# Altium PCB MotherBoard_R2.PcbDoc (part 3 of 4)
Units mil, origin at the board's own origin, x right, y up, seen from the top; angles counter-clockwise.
Board outline 9500 x 4600 mil, 4 copper layers (Top Layer, Power Layer, GND Layer, Bottom Layer), stack 61.6 mil thick; 206 components, 289 nets, 935 pads, 328 vias.
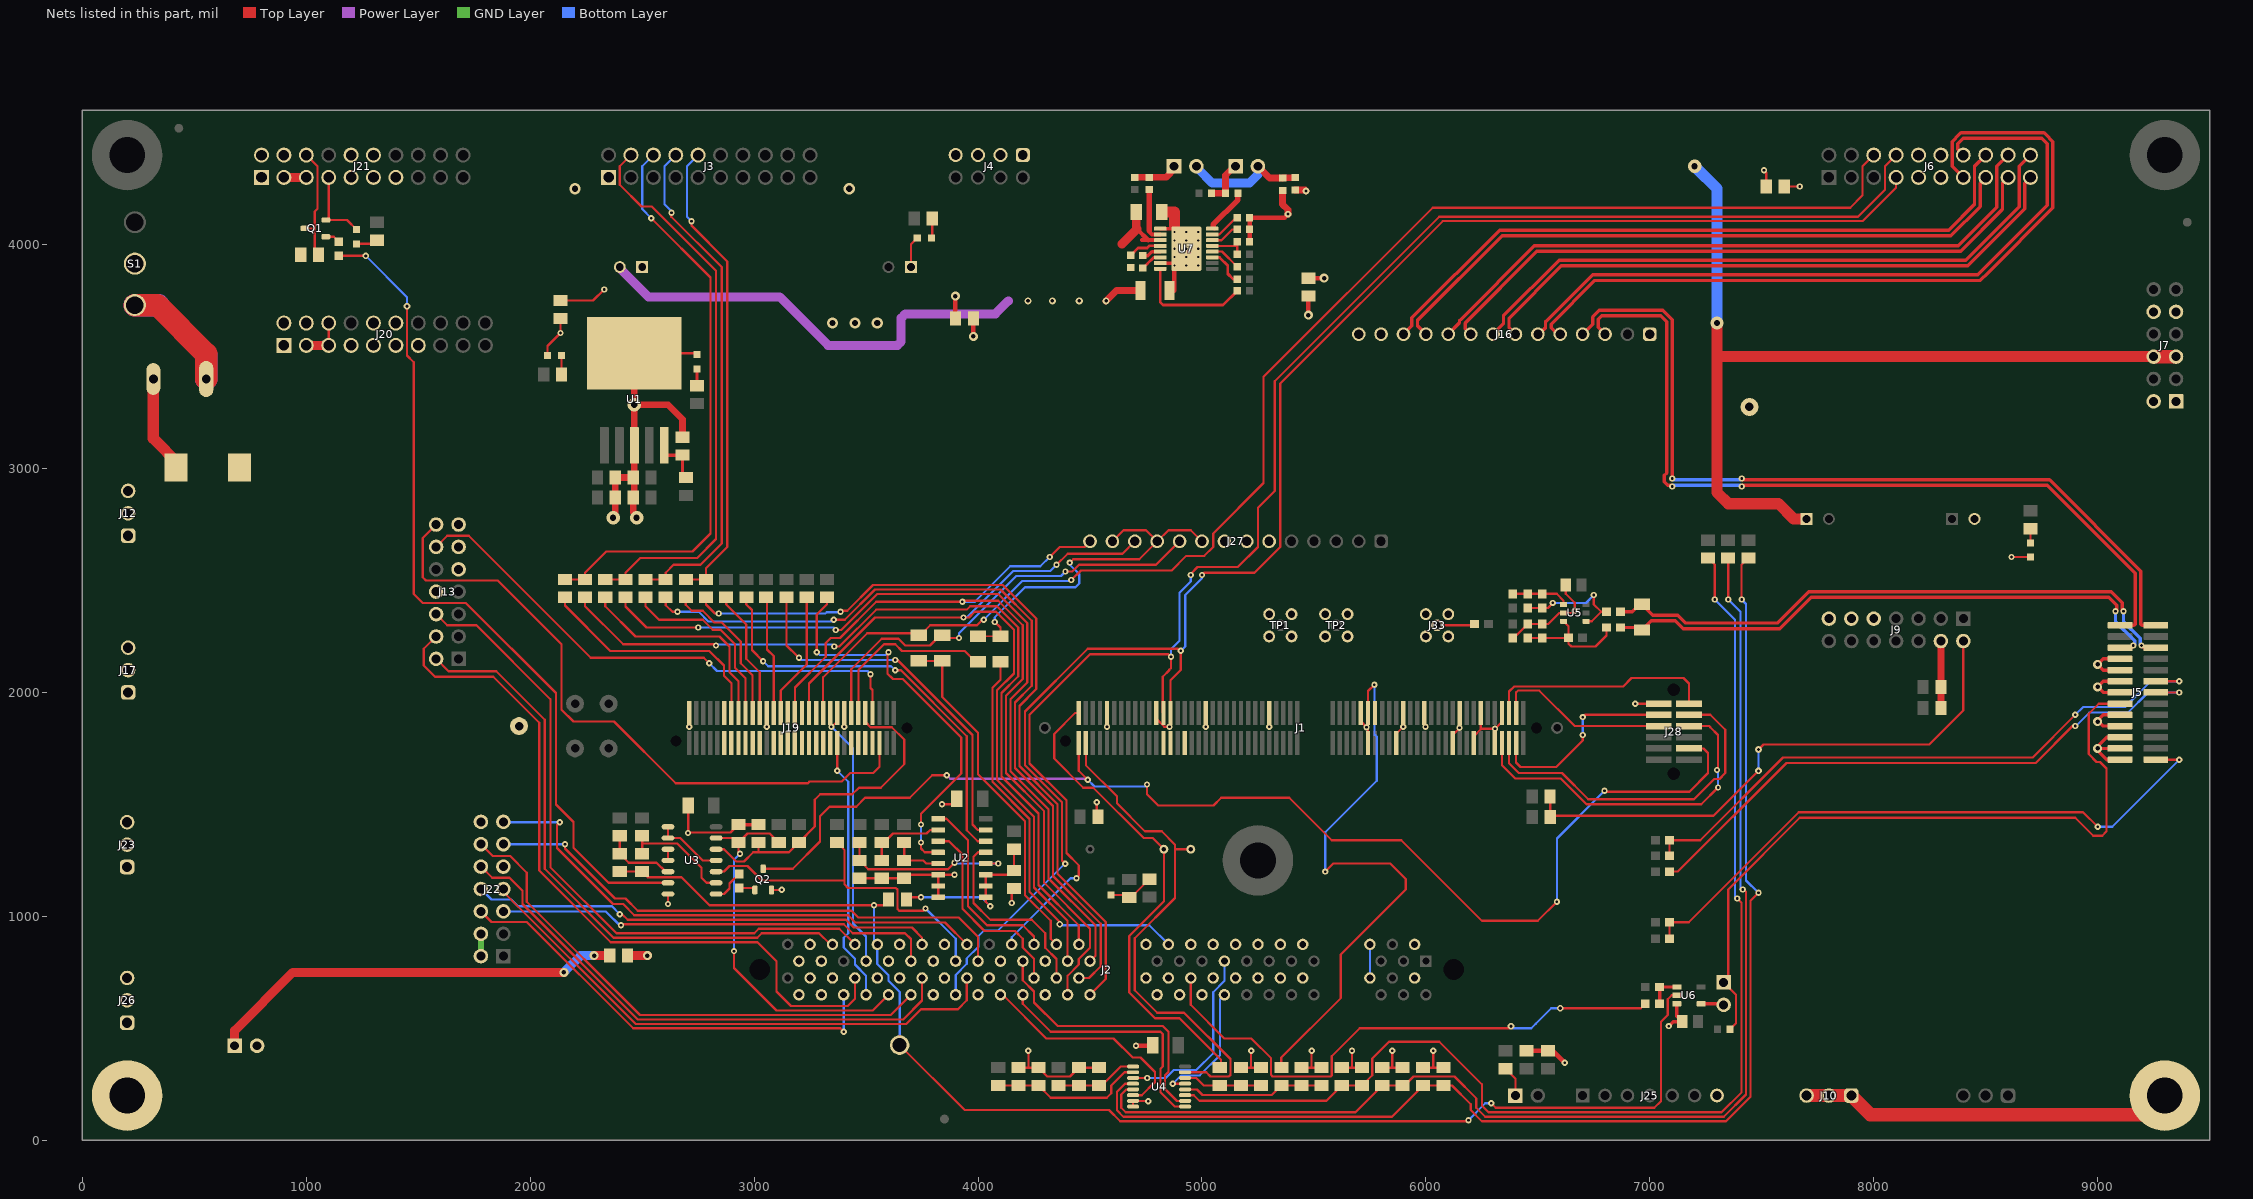
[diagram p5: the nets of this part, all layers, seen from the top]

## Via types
v1: diameter 28, hole 12, Top Layer to Bottom Layer, 238 vias
v2: diameter 40, hole 20, Top Layer to Bottom Layer, 21 vias
v3: diameter 30, hole 14, Top Layer to Bottom Layer, 19 vias
v4: diameter 28, hole 12, Top Layer to Bottom Layer, tented top, 16 vias
v5: diameter 22, hole 10, Top Layer to Bottom Layer, tented both sides, 12 vias
v6: diameter 60, hole 28, Top Layer to Bottom Layer, 9 vias
v7: diameter 50, hole 28, Top Layer to Bottom Layer, 5 vias
v8: diameter 32, hole 16, Top Layer to Bottom Layer, tented top, 4 vias
v9: diameter 22, hole 10, Top Layer to Bottom Layer, 3 vias
v10: diameter 30, hole 14, Top Layer to Bottom Layer, tented top, 1 vias

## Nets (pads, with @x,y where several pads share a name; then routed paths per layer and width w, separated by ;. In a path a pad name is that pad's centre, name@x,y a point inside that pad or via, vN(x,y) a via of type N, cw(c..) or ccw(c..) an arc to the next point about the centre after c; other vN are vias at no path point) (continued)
C2K_GPIO61: J13.14 J19.126 | length 2989.1
  Top Layer w10: J13.14@1579.98,2750 1520,2690.02 1520,2515 1535,2500 1855,2500 2139.92,2215.08 2139.92,1923.33 2193.25,1870 2374.61,1870 2649.61,1595 3240.05,1595 3247.17,1602.13 3391.55,1602.13 3429.42,1640 3532.01,1640 3560.01,1668 J19.126@3560.01,1775
C2K_GPIO62: J13.12 J19.127 | length 2393.2
  Top Layer w10: J13.12@1579.98,2650 1629.98,2700 1725,2700 2270,2155 2775,2155 v1(2800,2130) ; v1(3520,2081.76) 3520,2020 3528.51,2011.49 J19.127@3528.51,1908.86
  Bottom Layer w10: v1(2800,2130) 2834.25,2095.75 3506.01,2095.75 v1(3520,2081.76)
C2K_GPIO63: J19.128
C2K_GPIO64: J19.129 R30.1 R82.2 U3.12 | length 1513.4
  Top Layer w10: U3.12@2830,1300 2865,1300 2920,1245 2955,1245 2996,1286 3020,1286 ; R82.2@3020,1330 3020,1286 ; J19.129@3497.02,1908.86 3497.02,1867.98 3520,1845 3615,1845 3670,1790 3670,1680 3565,1575 3467.79,1575 3437.79,1545 3295,1545 3271,1521 3271,1401 R30.1@3200,1330 3156,1286 3020,1286
C2K_GPIO65: J19.130
C2K_GPIO66: J19.131 R85.1 | length 805.6
  Top Layer w10: J19.131@3465.52,1908.86 3465.52,2100.52 3580,2215 3630,2215 3660,2185 3940,2185 3987.23,2137.77 R85.1@4000,2137.77
C2K_GPIO67: J19.132
C2K_GPIO68: J19.133 J27.10 R21.2 | length 1945.3
  Top Layer w10: J19.133@3434.02,1908.86 3434.02,2104.02 3570,2240 3645,2240 3675,2210 3785,2210 3830,2255 R21.2@3840,2255 3851.99,2243.01 v1(3915,2243.01) ; v4(4390,2540) 4420.83,2540 4450.83,2570 4795,2570 J27.10@4900,2675
  Bottom Layer w10: v1(3915,2243.01) 3915,2265 4170,2520 4370,2520 v4(4390,2540)
C2K_GPIO69: J19.134
C2K_GPIO70: J2.43 J19.137 | length 1185.1
  Top Layer w10: v1(3345,1847.09) 3347.09,1847.09 3371.03,1871.03 J19.137@3371.03,1908.86
  Bottom Layer w10: v1(3345,1847.09) 3441.7,1750.39 3441.7,968.3 3500,910 J2.43@3500,800
C2K_GPIO71: J2.93 J19.138 | length 1195
  Top Layer w10: v1(3371.03,1650) J19.138@3371.03,1775
  Bottom Layer w10: v1(3371.03,1650) 3420,1601.03 3420,924.47 3400,904.47 3400,861.31 3450,811.31 3450,785.46 3500,735.46 J2.93@3500,650
C2K_GPIO72: J19.139
C2K_GPIO73: J19.140
C2K_GPIO74: J6.6 J19.141 R20.2 | length 6218.5
  Top Layer w10: J19.141@3308.04,1908.86 3308.04,2067.62 3505.42,2265 3725,2265 R20.2@3735,2255 3741.54,2255 3786.54,2300 3995,2300 4022.43,2327.43 4024.86,2325 v1(4025,2325) ; v4@4414.96,2502.47 v4(4416.75,2502.47) 4459.28,2545 4865.25,2545 4930.25,2610 5010,2610 5050,2650 5050,2710 5275,2935 5275,3410 6030,4165 7895,4165 7950,4220 7950,4350 J6.6@8000,4400
  Bottom Layer w10: v1(4025,2325) 4197.47,2497.47 4411.75,2497.47 v4(4416.75,2502.47)
C2K_GPIO76: J19.143
C2K_GPIO77: J19.144
C2K_GPIO78: J2.25 J19.145 J27.12 | length 3758.8
  Top Layer w10: J19.145@3245.05,1908.86 3245.05,2040.05 3540,2335 v1(3935.37,2335) 3960,2335 3985,2360 4080,2360 4160,2280 4160,2085 4085,2010 4085,1610.28 4250,1445.28 4250,1128.92 4400,978.92 J2.25@4400,800 ; v1(4350,2570) 4400,2620 4645,2620 J27.12@4700,2675
  Bottom Layer w10: v1(3935.37,2335) 3950,2335 4157.57,2542.57 4322.57,2542.57 v1(4350,2570)
C2K_GPIO79: J19.146
C2K_GPIO80: J19.147
C2K_GPIO81: J19.148
C2K_GPIO82: J2.75 J19.149 J27.14 | length 3938.7
  Top Layer w10: J19.149@3182.05,1908.86 3182.05,2022.05 3320,2160 3320,2221.24 3341.77,2243.01 3383.01,2243.01 3545,2405 v1@3925,2405 ; v1(3930,2405) 3925,2410 4090,2410 4200,2300 4200,2059.99 4125,1984.99 4125,1640 4295,1470 4295,1150 4500,945 4500,860 4450,810 4450,785 4400,735 J2.75@4400,650 ; v1(4320,2605) 4365,2650 4475,2650 J27.14@4500,2675
  Bottom Layer w10: v1(3930,2405) 3929.63,2405.37 3985.37,2405.37 4143.25,2563.25 4278.25,2563.25 v1(4320,2605)
C2K_GPIO83: J19.150
C2K_GPIO84: J19.151
C2K_GPIO85: J19.152
C2K_GPIO86: J19.153 R14.1 | length 564.2
  Top Layer w10: J19.153@3119.06,1908.86 3119.06,2009.06 3235,2125 R14.1@3235,2425
C2K_GPIO87: J19.154
C2K_GPIO88: J19.155 R18.1 | length 528.6
  Top Layer w10: R18.1@3057.6,2425 3057.6,2192.4 3087.57,2162.43 J19.155@3087.57,1908.86
C2K_GPIO89: J19.156
C2K_GPIO90: J19.159 R16.1 | length 578.1
  Top Layer w10: R16.1@2875,2425 2875,2393.09 2965,2303.09 2965,2150 3024.57,2090.43 J19.159@3024.57,1908.86
C2K_GPIO91: J19.160
C2K_GPIO92: J19.161 R12.1 | length 686.9
  Top Layer w10: R12.1@2695,2425 2695,2391.87 2721.87,2365 2770,2365 2822.4,2312.6 2855,2312.6 2940,2227.6 2940,2130 2993.08,2076.92 J19.161@2993.08,1908.86
C2K_GPIO93: J19.162
C2K_GPIO94: J19.163 R10.1 | length 835.9
  Top Layer w10: R10.1@2515,2425 2515,2385 2575,2325 2770,2325 2815,2280 2850,2280 2915,2215 2915,2110 2961.58,2063.42 J19.163@2961.58,1908.86
C2K_GPIO95: J19.168
C2K_GPIO96: J1.93 J2.85 J6.7 | length 7357.5
  Top Layer w10: v1(4389.32,1235.68) 4375,1250 4375,1510 4210,1675 4210,1915 4490,2195 4891.51,2195 4900.75,2185.75 v1(4905,2185.75) 4905,2100 4859.45,2054.45 J1.93@4859.45,1908.86 ; v4(5000,2525) 5010,2535 5235,2535 5350,2650 5350,3380 6075,4105 7949.79,4105 8100,4255.21 J6.7@8100,4300
  Bottom Layer w10: J2.85@3900,650 3900,738.54 3950,788.54 3950,812.46 4001,863.46 4001,911 4026,936 4088,936 4387.68,1235.68 v1(4389.32,1235.68) ; v1(4905,2185.75) 4925,2205.75 4925,2435 5000,2510 v4(5000,2525)
C2K_GPIO97: J1.94
C2K_GPIO98: J1.95 J2.30 J6.8 | length 7054.7
  Top Layer w10: v1(4440,1170) 4450,1180 4450,1227.85 4395,1282.85 4395,1518.28 4230,1683.28 4230,1900 4500.23,2170.23 4850.23,2170.23 v1(4861.45,2159.02) 4861.45,2108.69 4853.88,2101.12 4855,2100 4825,2070 4825,1911.81 J1.95@4827.95,1908.86 ; v4(4950,2525) 4950,2529.57 4980.43,2560 5160,2560 5250,2650 5250,2825 5325,2900 5325,3390 6060,4125 7930,4125 8050,4245 8050,4350 J6.8@8100,4400
  Bottom Layer w10: J2.30@4150,875 4150,907 4413,1170 v1(4440,1170) ; v1(4861.45,2159.02) 4861.45,2192.78 4900,2231.33 4900,2445.39 4950,2495.39 v4(4950,2525)
C2K_GPIO99: J1.96
C2K_GPIO104: J19.169
C2K_GPIO107: J19.170
C2K_GPIO125: J1.90
C2K_GPIO126: J19.142
C2K_GPIO127: J19.165 R6.1 | length 982.3
  Top Layer w10: R6.1@2335,2425 2335,2385 2470,2250 2845,2250 2890,2205 2890,2090 2930.09,2049.91 J19.165@2930.09,1908.86
C2K_GPIO128: J19.166
C2K_GPIO133: J19.164
C2K_GPIO147: J19.167 R8.1 | length 1082.7
  Top Layer w10: R8.1@2155,2425 2155,2388.6 2358.94,2184.66 2800.34,2184.66 2865,2120 2865,2074.44 2898.59,2040.85 J19.167@2898.59,1908.86
C2K_TCK: J1.5 J28.2 | length 1024.4
  Top Layer w10: J1.5@6371.26,1908.86 6371.26,2003.86 6393.55,2026.15 6879.86,2026.15 6918.71,2065 7150,2065 7175,2040 J28.2@7175,1950
C2K_TDI: J1.8 J28.6 | length 1552.9
  Top Layer w10: J1.8@6339.76,1775 6339.76,1675.24 6399,1616 6602,1616 6717,1501 7230,1501 v1(7305,1576) ; J28.6@7175,1850 7265,1850 7270,1845 7305,1810 7305,1666 7300,1661 v1(7300,1654)
  Bottom Layer w10: v1(7300,1654) 7300,1645 7305,1640 v1(7305,1576)
C2K_TDO: J1.6 J28.4 | length 1554.8
  Top Layer w10: J1.6@6371.26,1775 6371.26,1683.74 6415,1640 6608,1640 6725,1523 7197,1523 7288,1614 7311,1614 7337,1640 7337,1833 7270,1900 J28.4@7175,1900
C2K_TMS: J1.3 J28.5 | length 797.5
  Top Layer w10: J1.3@6402.76,1908.86 6402.76,2000.24 6410.8,2008.28 6506.02,2008.28 6664.29,1850 J28.5@7039.96,1850
C2K_TRSTn: J1.4 J28.3 | length 889.6
  Top Layer w10: J1.4@6402.76,1775 6402.76,1687.24 6422.69,1667.31 6582.31,1667.31 6700,1785 v1(6700,1810) ; v1@6700,1885 v1@6702.5,1887.5 ; v1(6700,1890) 6710,1900 J28.3@7039.96,1900
  Bottom Layer w10: v1(6700,1810) v1@6700,1885
C2K_VDD: J1.118 TP3.1 U4.15 | length 2296.9
  Top Layer w10: J1.118@4481.5,1775 4481.5,1675.27 4620,1536.77 4620,1505 4745,1380 4820,1380 4880,1320 4880,1300 ; U4.15@4924.56,303.98 5018.66,303.98 5037.64,285 5119.92,285 5127,292.08 5127,363 4920,570 4800,570 4700,670 4700,902.3 4880,1082.3 4880,1300 ; TP3.1@4950,1300 4880,1300
C2K_VDDIO: J1.119 R39.2 TP4.1 | length 2190.3
  Top Layer w10: J1.119@4450,1908.86 4433.86,1908.86 4340,1815 4340,1705 4470,1575 4515,1575 4740,1350 4780,1350 TP4.1@4830,1300 4830,1067.75 4675,912.75 4675,660 4790,545 4900,545 5084.41,360.59 R39.2@5084.41,324.57
C2K_VREFHI: J1.45 R38.2 | length 2548.6
  Top Layer w10: R38.2@5354.41,324.57 5354.41,369.41 5620,635 5620,830 5910,1120 5910,1167.21 5841.21,1236 5586,1236 v1(5550,1200) ; J1.45@5741.34,1908.86 5741.34,2006.34 v1(5770,2035)
  Bottom Layer w10: v1(5550,1200) 5550,1376.1 5780,1606.1 5780,1802.31 5770,1812.31 v1(5770,2035)
C2K_VREFLO: J1.43
C2K_XRSn: J1.120 J28.10 Q2.3 | length 5600.5
  Top Layer w10: Q2.3@3040.4,1212.49 3172.49,1212.49 3294,1334 3294,1447 3337,1490 3455.59,1490 3495.59,1530 3695,1530 3795,1630 v4(3860,1630) ; J1.120@4450,1775 4450,1650 v1(4490,1610) ; v1(4754.63,1589.25) 4754.63,1545.37 4805,1495 5051.58,1495 5086.58,1530 5390,1530 5580,1340 5890,1340 6250,980 6500,980 v1(6585,1065) ; v1(6798,1561) v1@6802,1557 ; v1@6801,1556 v1@6802,1557 ; J28.10@7175,1750 7240,1750 7260,1730 7260,1640 7177,1557 v1@6802,1557
  Power Layer w10: v4(3860,1630) 3875.68,1614.32 4485.68,1614.32 v1(4490,1610)
  Bottom Layer w10: v1(4490,1610) 4520,1580 4745.37,1580 v1(4754.63,1589.25) ; v1@4756.32,1588.25 v1@4757.32,1587.25 ; v1(6585,1065) 6585,1348 v1(6798,1561)
CAN_GPIO1: J2.84 J22.7 | length 2483.7
  Top Layer w10: J22.7@1879.98,1122.3 1879.98,1110.02 2470,520 3680,520 3745,585 3910,585 3950,625 J2.84@3950,725 J2.84@3963.46,725
CAN_GPO2: J2.33 J22.11 | length 2411.4
  Top Layer w10: v1(2155,1322.3) 2155,1303.14 2378.14,1080 2425,1080 2480,1025 3435,1025 3465,995 3914,995 4000,909 J2.33@4000,800
  Bottom Layer w10: J22.11@1879.98,1322.3 v1(2155,1322.3)
CAN_nINT: J2.34 J22.13 | length 2381.6
  Top Layer w10: v1(2132.35,1420) 2120,1407.65 2120,1305 2370,1055 2415,1055 2465,1005 3420,1005 3452.13,972.87 3852.13,972.87 J2.34@3950,875
  Bottom Layer w10: J22.13@1879.98,1422.3 1882.28,1420 v1(2132.35,1420)
CAN_nWRKQ: J22.9
Clr_OCP_Latch: J27.9 J27.11 J27.13 R85.2 R86.2 | length 1656.2
  Top Layer w10: R85.2@4000.03,2250.2 R86.2@4100,2251.94 ; v1(4075,2315) 4100,2290 R86.2@4100,2251.94 ; v1(4410,2580) 4425,2595 4720,2595 J27.11@4800,2675 ; J27.13@4600,2675 4650,2725 4750,2725 J27.11@4800,2675 ; J27.9@5000,2675 4950,2725 4850,2725 J27.11@4800,2675
  Bottom Layer w10: v1(4075,2315) 4075,2335.39 4209.61,2470 4435,2470 4452,2487 4452,2528.68 4410,2570.68 v1(4410,2580)
CT_N: J5.6 R57.1 R61.2 | length 2664.8
  Top Layer w15: R57.1@6869.5,2360 6921.08,2360 6954.17,2393.09 R61.2@6965,2393.09 7013.09,2345 7125,2345 7160,2310 7570,2310 7710,2450 7720.83,2450 7721.21,2450.37 8143.5,2450.37 8143.87,2450 9060.36,2450 9110,2400.36 9110,2365 9111.77,2363.23 v1(9115.44,2363.23) ; v1(9195.44,2210) 9205.44,2200 J5.6@9260.24,2200
  Bottom Layer w15: v1(9115.44,2363.23) 9115.44,2316.42 9190,2241.85 9190,2214.63 9194.63,2210 v1(9195.44,2210)
CT_P: J5.5 R61.1 R64.1 | length 2610.6
  Top Layer w15: R64.1@6869.5,2290 6935,2290 6946.09,2278.91 R61.1@6965,2278.91 7006.09,2320 7114.64,2320 7149.64,2285 7580.36,2285 7720.36,2425 7731.19,2425 7731.56,2425.37 8133.14,2425.37 8133.52,2425 9050,2425 9085,2390 9085,2365 9083.23,2363.23 v1(9079.56,2363.23) ; J5.5@9100,2200 9149.56,2200 v1(9159.56,2210)
  Bottom Layer w15: v1(9079.56,2363.23) 9079.56,2316.93 9165,2231.5 9165,2214.63 9160.37,2210 v1(9159.56,2210)
EARTH: H2.1 J10.1 J10.2 J10.3 | length 1670.4
  Top Layer w60: J10.3@7700,200 J10.2@7800,200 J10.1@7900,200 7985,115 9215,115 H2.1@9300,200
EARTH1: H3.1 J12.1 J12.2 J12.3 J17.1 J17.2 J17.3 J23.1 J23.2 J23.3 J26.1 J26.2 J26.3
EN-EXT1: J20.3 J20.5 J20.6 | length 200
  Top Layer w10: J20.5@1100,3550 J20.6@1100,3650
  Top Layer w40: J20.3@1000,3550 J20.5@1100,3550
EN-EXT2: J21.6 Q1.3 R31.1 | length 523.9
  Top Layer w10: Q1.3@992.86,4072.6 1035.56,4072.6 1037.97,4075 ; J21.6@1000,4400 1050,4350 1050,4160 1037.97,4147.97 1037.97,4075 ; R31.1@1055,3955 1037.97,3972.03 1037.97,4075
EN_1: J5.15 J34.1 R84.1 | length 3257
  Top Layer w10: R84.1@7357.56,495 7385,522.44 7385,650 J34.1@7330,705 7350,725 7350,1120 7670,1440 8900,1440 8980,1360 9020,1360 9040,1380 9040,1660 9010,1690 8995,1690 8960,1725 8960,1905 9005,1950 J5.15@9100,1950
EN_DRV: J2.42 R35.1 R36.1 R54.2 TP6.1 U6.2 | length 6055.2
  Top Layer w10: R35.1@2400,1200 R36.1@2500,1200 2525,1175 2675.83,1175 2800.83,1050 v1(3535,1050) 3575,1050 R54.2@3600,1075 ; TP6.1@3650,465 TP6.1@3650,425 3940,135 4585,135 4635,85 6185,85 v1(6190,90) ; v1(6292.29,165) 6312.29,145 6360,145 7020,145 7050,175 7050,530 7080,560 7080,630 7097.4,647.4 U6.2@7120.73,647.4
  Bottom Layer w10: v1(3535,1050) 3535,890 J2.42@3550,875 3550,787.29 3600,737.29 3600,712.71 3650,662.71 TP6.1@3650,465 ; v1(6190,90) 6265,165 v1(6292.29,165)
EXC: J9.2 R4.2 R5.2 | length 2491.8
  Top Layer w10: R5.2@6554.76,1535 6555,1534.76 6555,1449 7284,1449 v3(7485,1650) ; v3(7485,1745) 7508,1768 8248.35,1768 8400,1919.65 J9.2@8400,2229.7
  Bottom Layer w10: v3(7485,1650) v3(7485,1745)
GND: C1.2 C2.2 C3.1 C4.2 C5.2 C6.1 C7.2 C8.1 C9.1 C10.1 C11.1 C12.1 C13.1 C14.1 C16.2 C17.2 C18.2 C19.2 C20.2 C21.2 C24.1 D1.1 D2.1 D3.1 D4.1 D5.1 D7.2 GP1.1 GP2.1 J1.7 J1.10 J1.13 J1.16 J1.19 J1.22 J1.29 J1.35 J1.38 J1.46 J1.47 J1.65 J1.83 J1.97 J1.111 J2.8 J2.10 J2.12 J2.14 J2.27 J2.37 J2.47 J2.58 J2.60 J2.62 J2.64 J3.1 J4.1 J4.3 J4.5 J4.7 J5.7 J5.9 J5.11 J5.13 J5.17 J5.19 J5.21 J5.23 J5.25 J6.9 J6.10 J6.11 J6.12 J7.1 J7.2 J7.5 J7.6 J7.9 J7.10 J9.9 J9.11 J9.13 J13.8 J13.9 J13.11 J13.13 J14.2 J16.1 J16.13 J16.14 J19.135 J19.157 J19.179 J20.7 J20.9 J20.11 J20.12 J20.13 J21.7 J21.9 J21.11 J21.12 J21.13 J22.2 J22.4 J24.2 J25.7 J27.6 J27.7 J27.8 J28.1 J29.1 J30.1 J31.1 J32.2 J33.2 J33.3 J33.4 J33.5 Q1.2 Q2.2 R23.1 R26.1 R27.1 R28.1 R45.1 R47.1 R48.1 R49.1 R50.1 R51.1 R52.1 R53.1 R66.1 R67.1 R67.2 R68.1 R68.2 R69.1 R69.2 R70.1 R70.2 R81.1 R82.1 R90.1 R91.1 R92.1 R98.1 R99.1 R102.1 R103.2 TP1.2 TP1.3 TP1.4 TP1.5 TP2.2 TP2.3 TP2.4 TP2.5 U1.3 U1.6 U2.6 U2.7 U2.8 U3.7 U4.7 U4.8 U5.2 U6.3 U7.9 U7.15 U7.17@4930,3981.63 | length 14754.7
  Top Layer w10: J21.7@1100,4300 1100,4122.65 Q1.2@1087.35,4110 1181.69,4110 D3.1@1225,4066.69 ; D2.1@2077.01,3505 2077.01,3547.21 v1(2134.8,3605) R70.1@2134.8,3670 ; R70.2@2136,3751.2 R70.2@2134.8,3750 2280,3750 v1(2330,3800) ; U1.6@2465,3515 2738.36,3515 D4.1@2745,3508.36 ; v1(2615,1055) 2615.43,1055.43 U3.7@2615.43,1100 ; v1(2705,1372.3) v1@2705.83,1373.13 ; C6.1@2705.83,1495 v1@2705.83,1373.13 ; v1(2709.61,1847.09) J19.179@2709.61,1908.86 ; R81.1@2930.09,1410 2894.77,1374.68 2707.38,1374.68 v1@2705.83,1373.13 ; v1(3056.07,1847.09) J19.157@3056.07,1908.86 ; Q2.2@3077.8,1118 3122,1118 v1(3123,1119) ; v1(3402.53,1847.09) J19.135@3402.53,1908.86 ; R26.1@3470,1170 R27.1@3570,1170 R28.1@3670,1170 3686,1186 U2.6@3821.7,1186 ; J29.1@3700,3900 3700,4001.5 D1.1@3728.5,4030 ; U2.8@3821.7,1086 U2.7@3821.7,1136 U2.6@3821.7,1186 ; v1(3839.17,1501.21) 3882.04,1501.21 C5.2@3905.83,1525 ; R69.2@3899.07,3670 3900,3670.93 R69.2@3899.07,3671.85 ; v1@3900,1186 v1(3895,1186) U2.6@3821.7,1186 ; v1(4150,1060) R45.1@4150,1125 ; R53.1@4180,324.57 4225,324.57 ; v1(4224,399.41) 4225,398.41 4225,324.57 ; R103.2@4530,1450 v1(4530,1510) ; C11.1@4540,324.57 R50.1@4450,324.57 4410.43,285 4309.57,285 C14.1@4270,324.57 4225,324.57 ; v1(4575.98,1847.09) J1.111@4575.98,1908.86 ; U4.8@4692.28,150.43 U4.7@4692.28,176.02 4693.3,175 v1(4760,175) ; J1.97@4796.46,1908.86 4796.46,1881.54 4830.91,1847.09 v1(4855,1847.09) ; v1(5016.93,1847.09) J1.83@5016.93,1908.86 ; R48.1@5174.41,324.57 5219.41,324.57 ; v1(5220,399.41) 5219.41,398.82 5219.41,324.57 ; C9.1@5264.41,324.57 5219.41,324.57 ; v1(5300,1847.09) 5300.39,1847.48 J1.65@5300.39,1908.86 ; R47.1@5444.41,324.57 5489.41,324.57 ; R68.2@5470,3855 R68.2@5475,3850 ; v1(5490,400) 5489.41,399.41 5489.41,324.57 ; C8.1@5534.41,324.57 5489.41,324.57 ; C10.1@5624.41,324.57 5670,324.57 ; v1(5670,399.41) 5670,324.57 ; J1.47@5709.84,1908.86 5709.84,1870.16 v1(5735,1845) 5741.34,1838.66 J1.46@5741.34,1775 ; R49.1@5710,328.98 5714.41,333.39 R49.1@5714.33,333.46 ; R49.1@5714.41,324.57 5670,324.57 ; R51.1@5805,324.57 5850,324.57 ; v1(5850,400) 5850,324.57 ; J1.38@5867.32,1775 5867.32,1815.59 v1(5898.82,1847.09) J1.35@5898.82,1908.86 ; C12.1@5895,324.57 5850,324.57 ; R52.1@5987.8,324.57 6032.8,324.57 ; v1@5993.31,1847.09 J1.29@5993.31,1908.86 ; v1(6032.8,400) 6032.8,324.57 ; C13.1@6077.8,324.57 6032.8,324.57 ; J1.22@6119.29,1775 6119.29,1809.29 6150,1840 v1(6150,1841.93) 6150,1842.28 6150.79,1843.07 J1.19@6150.79,1908.86 ; J1.16@6213.78,1775 6213.78,1803.78 6245.28,1835.28 6245.28,1837.72 ; J1.13@6245.28,1908.86 6245.28,1837.72 ; J1.10@6308.27,1775 v1(6308.27,1838.27) ; J1.7@6339.76,1908.86 6339.76,1869.76 v1(6308.27,1838.27) ; C17.2@6388.23,2243.01 6392.01,2243.01 C18.2@6455,2306 R66.1@6520,2306 6546,2306 6595,2355 U5.2@6614.8,2355 6654.29,2355 v1(6664.29,2365) 6664.29,2400.71 6624.57,2440.43 C16.2@6624.57,2480 ; v1(6935,1950) J28.1@7039.96,1950 ; v1(7510,4331.92) 7520,4321.92 R67.1@7520,4259.64 ; R67.2@7600,4259.64 7659.64,4259.64 7660,4260 v1(7670,4260) ; v1(8615,2605) D5.1@8700,2605 ; 6245.28,1837.72 6281.18,1837.72 6281.73,1838.27 v1(6308.27,1838.27)
  Top Layer w15: R81.1@2930.09,1410 R82.1@3020,1410 ; U7.15@4813.86,3917.65 U7.17@4866.02,3917.65 ; v1(7085,510) 7105,530 C19.2@7144.57,530 7120.73,553.83 U6.3@7120.73,610 ; v2@9000,1874.8 9025.2,1900 J5.17@9100,1900 ; v2@9002.5,1872.3 9024.8,1850 J5.19@9100,1850 ; J5.25@9100,1700 9040.39,1700 9000,1740.39 v2(9000,1750) ; J5.23@9100,1750 v2(9000,1750) ; J5.21@9100,1800 9040,1800 9000,1760 v2(9000,1750) ; J5.13@9100,2000 9025.39,2000 v2(9000,2025.39) 9024.61,2050 J5.11@9100,2050 ; J5.9@9100,2100 9025,2100 v2(9000,2125) 9025,2150 J5.7@9100,2150
  Top Layer w17: U7.9@4813.86,4071.2 U7.17@4876.85,4071.2
  Top Layer w20: R69.2@3899.07,3671.85 v2(3899.07,3770) ; v2@3979.07,3600 R69.1@3979.07,3670 ; v1(4705,422.3) 4778.13,422.3 C7.2@4780.83,425 ; C20.2@4844.96,3795 C20.2@4854.96,3795 4876.85,3795 v5(4876.85,3906.82) v5(4930,3906.82) v9(4930,3944.23) v9(4930,3981.63) ; U7.17@4880,4071.2 4930,4021.2 v9(4930,4019.03) v9(4930,3981.63) ; v5(4983.15,3906.82) 4983.15,3928.48 v9(4930,3981.63) ; R90.1@5212.56,4013.15 R91.1@5212.56,4067.92 R92.1@5212.56,4121.03 5369.27,4121.03 v3(5384.27,4136.03) ; v2(5475,3685) R68.1@5475,3770 ; R68.2@5475,3850 v2(5545,3850) ; R102.1@6455,400 C24.1@6545,400 6566.78,400 v1(6620,346.78)
  Top Layer w30: v6@2380,2790 C2.2@2380,2870 C1.2@2380,2960 C4.2@2460,2960 ; U1.6@2465,3515 v6(2465,3285) ; v6@2475,2790 2460,2805 C3.1@2460,2870 2465,2875 U1.3@2465,3103.58 v6(2465,3285) ; R23.1@2680,3140 2680,3220 2615,3285 v6(2465,3285) ; R98.1@5360,4242.7 5360,4180 5384.27,4155.73 v3(5384.27,4136.03) ; R99.1@5416.01,4244.17 5460.83,4244.17 v3(5465,4240)
  Top Layer w50: J14.2@316.89,3400 316.89,3133.62 431.89,3018.62 D7.2@418.27,3005 ; C21.2@4820.72,4146.03 4876.85,4146.03 4876.85,4085 ; v6(7300,3650) 7300,3500 ; J31.1@7700,2775 7642.68,2775 7574.68,2843 7350.25,2843 7300,2893.25 7300,3500 ; J7.6@9250,3500 7300,3500
  Top Layer w60: J7.6@9250,3500 J7.5@9350,3500
  GND Layer w25: J22.2@1779.98,822.3 J22.4@1779.98,922.3
  Bottom Layer w50: v6@7206.54,4343.46 7300,4250 v6(7300,3650)
  other v1: 5998.31,1847.09
  other v2: 9000,1869.8 3979.07,3590
  other v5: 4876.85,3944.23 4983.15,3944.23 4876.85,3981.63 4983.15,3981.63 4876.85,4019.03 4983.15,4019.03 4876.85,4056.43 4930,4056.43 4983.15,4056.43
  other v6: 2370,2780 2475,2780 7200,4350
  other v7: 3350,3650 3450,3650 3550,3650 2200,4250 3425,4250
GND_ISO: J2.6 J2.56 | length 150
  Bottom Layer w10: J2.56@5750,725 J2.6@5750,875
GPIO_RST: J2.95 J22.6 | length 2014.7
  Top Layer w10: J22.6@1779.98,1022.3 1827.28,975 1985,975 2460,500 3385,500 v1(3400,485)
  Bottom Layer w10: v1@3400,480 v1(3400,485) 3400,644.95 3402.53,647.47 J2.95@3400,650
Ia_N: J6.20 J16.8 | length 2857.6
  Top Layer w15: J16.8@6300,3600 6346.26,3646.26 6346.26,3681.62 6594.64,3930 8410.19,3930 8650,4169.81 8650,4350 J6.20@8700,4400
Ia_P: J6.19 J16.7 | length 2740
  Top Layer w15: J16.7@6400,3600 6371.26,3628.74 6371.26,3671.26 6605,3905 8420.54,3905 8675,4159.46 8675,4275 J6.19@8700,4300
Ib_N: J6.18 J16.10 | length 2944.5
  Top Layer w15: J16.10@6100,3600 6150,3650 6150,3660.36 6157.32,3667.68 6484.64,3995 8377.72,3995 8550,4167.28 8550,4350 J6.18@8600,4400
Ib_P: J6.17 J16.9 | length 2823.8
  Top Layer w15: J16.9@6200,3600 6175,3625 6175,3650 6495,3970 8388.07,3970 8575,4156.93 8575,4275 J6.17@8600,4300
Ic_N: J6.16 J16.12 | length 3051.4
  Top Layer w15: J16.12@5900,3600 5937.5,3637.5 5937.5,3672.86 6329.64,4065 8334.61,4065 8450,4180.39 8450,4350 J6.16@8500,4400
Ic_P: J6.15 J16.11 | length 2941.1
  Top Layer w15: J16.11@6000,3600 5962.5,3637.5 5962.5,3662.5 6340,4040 8344.96,4040 8475,4170.04 8475,4275 J6.15@8500,4300
NetC8_2: C8.2 R38.1 R47.2 U4.12 | length 637.7
  Top Layer w10: U4.12@4924.56,227.2 4977.8,227.2 5002.8,202.2 5312.05,202.2 R38.1@5354.41,244.57 R47.2@5444.41,244.57 C8.2@5534.41,244.57
NetC9_2: C9.2 R39.1 R48.2 U4.14 | length 353.9
  Top Layer w10: U4.14@4924.56,278.39 4974.04,278.39 5007.86,244.57 R39.1@5079.41,244.57 5084.41,244.57 R48.2@5174.41,244.57 C9.2@5264.41,244.57
NetC10_2: C10.2 R43.1 R49.2 U4.11 | length 5328.6
  Top Layer w10: U4.11@4924.56,201.61 4963.39,201.61 4988.39,176.61 5556.46,176.61 C10.2@5624.41,244.57 R49.2@5714.41,244.57 5760,290.16 5760,365 5835,440 6060,440 6250,250 6250,155 6280,125 7320,125 7410,215 7410,1059.32 ; R43.1@7260,2600 7290,2570 v1(7290,2415) ; v1(7390,1080) 7410,1060
  Bottom Layer w10: v1(7290,2415) 7380,2325 7380,2045 7380,1090 ; v1@7380,1080 7380,1090 ; v1(7390,1080) 7380,1090
NetC11_2: C11.2 R41.1 R50.2 U4.1 | length 367.5
  Top Layer w10: R41.1@4360,244.57 C11.2@4540,244.57 4552.05,244.57 4637.05,329.57 U4.1@4692.28,329.57
NetC12_2: C12.2 R42.1 R51.2 U4.5 | length 5572
  Top Layer w10: U4.5@4692.28,227.2 4662.2,227.2 4640,205 4640,145 4660,125 5685.43,125 R51.2@5805,244.57 C12.2@5895,244.57 5904.57,244.57 5945,285 6127.28,285 6225,187.28 6225,145 6265,105 7330,105 7430,205 7430,1110 7420,1120 v1(7415,1120) ; v1(7350,2415) 7350,2590 7345,2595 R42.1@7350,2600
  Bottom Layer w10: v1(7350,2415) 7405,2360 7405,2045 7405,1130 ; v1@7405,1120 7405,1130 ; v1(7415,1120) 7405,1130
NetC13_2: C13.2 R40.1 R52.2 U4.4 | length 5664.3
  Top Layer w10: U4.4@4692.28,252.8 4656.46,252.8 4620,216.34 4620,133.98 4648.98,105 5848.23,105 R52.2@5987.8,244.57 C13.2@6077.8,244.57 6116.22,244.57 6200,160.79 6200,135 6250,85 7340,85 7450,195 7450,1070 v1(7485,1105) ; v1(7410,2415) 7410,2570 R40.1@7440,2600
  Bottom Layer w10: v1(7410,2415) 7430,2395 7430,2045 7430,1190 7430,1160 v1(7485,1105) v1@7485,1110
NetC14_2: C14.2 R46.1 R53.2 U4.2 | length 692.2
  Top Layer w10: R46.1@4090,244.57 C14.2@4270,244.57 4324.57,190 4574.33,190 4594.67,210.33 4594.67,244.67 4653.98,303.98 U4.2@4692.28,303.98
NetC15_1: C15.1 R3.2 R60.1 U5.1 | length 256.9
  Top Layer w10: R60.1@6388.23,2440.39 R3.2@6455,2440.39 C15.1@6520,2440.39 6584.61,2440.39 6614.8,2410.2 U5.1@6614.8,2392.4
NetC15_2: C15.2 R3.1 R57.2 U5.4 | length 516.6
  Top Layer w10: R3.1@6455,2377.4 C15.2@6520,2377.4 6545,2377.4 6566.81,2399.21 v1(6566.81,2400) ; U5.4@6715.2,2317.6 6740.47,2317.6 6782.87,2360 ; v1(6749.66,2435) 6749.66,2393.21 6782.87,2360 ; R57.2@6806.51,2360 6782.87,2360
  Bottom Layer w10: v1(6566.81,2400) 6714.66,2400 v1(6749.66,2435)
NetC18_1: C18.1 R62.1 R64.2 R66.2 U5.3 | length 522.9
  Top Layer w10: C18.1@6455,2243.01 R66.2@6520,2243.01 6635.02,2243.01 R62.1@6637.01,2245 ; U5.3@6614.8,2317.6 6637.01,2295.39 R62.1@6637.01,2245 ; R64.2@6806.51,2290 6806.51,2253.93 6757.58,2205 6650,2205 6637.01,2217.99 R62.1@6637.01,2245
NetC22_2: C22.2 U7.12 | length 148.9
  Top Layer w12: C22.2@4682.3,3952.56 4714.74,3985 4755,3985 4764.42,3994.42 U7.12@4813.86,3994.42
NetC23_1: C23.1 U7.13 | length 85.4
  Top Layer w15: C23.1@4736,3950.56 4758.29,3950.56 4776.57,3968.83 U7.13@4813.86,3968.83
NetC23_2: C23.2 U7.14 | length 97.7
  Top Layer w12: C23.2@4736,3895.44 4754.27,3913.71 4755,3913.71 4784.53,3943.24 U7.14@4813.86,3943.24
NetD1_2: D1.2 R73.1 | length 88.2
  Top Layer w10: D1.2@3791.5,4030 3795,4033.5 R73.1@3795,4116.75
NetD2_2: D2.2 R74.1 | length 85
  Top Layer w10: R74.1@2140,3420 D2.2@2140,3505
NetD3_2: D3.2 R75.1 | length 96.8
  Top Layer w10: D3.2@1225,4003.7 1298.7,4003.7 R75.1@1315,4020
NetD4_2: D4.2 R76.1 | length 75.4
  Top Layer w12: R76.1@2745,3370 D4.2@2745,3445.37
NetD5_2: D5.2 R77.1 | length 63.3
  Top Layer w10: D5.2@8700,2667.99 R77.1@8700,2731.32
NetD6_2: D6.2 R78.1 R101.2 | length 208.2
  Top Layer w10: D6.2@4594.67,1095.5 4664.5,1095.5 R101.2@4675,1085 4684,1085 R78.1@4765,1166
NetJ9_4: J9.4 R79.2 R80.2 | length 299.7
  Top Layer w30: R79.2@8300,1930 R80.2@8300,2025 J9.4@8300,2229.7
NetJ11_1: J11.1 R94.2 R96.2 | length 184.9
  Top Layer w30: R94.2@5042.56,4229.87 5104.79,4229.87 R96.2@5104.92,4230 5104.92,4309.92 J11.1@5135,4340
NetJ11_2: J11.2 J15.2 R98.2 R99.2 | length 534.4
  Top Layer w30: J11.2@5235,4340 5260,4340 5302.18,4297.82 R98.2@5345,4297.82 ; R98.2@5360,4297.82 5361.47,4299.29 R99.2@5416.01,4299.29
  Bottom Layer w40: J15.2@4980,4341.25 5046.25,4275 5212.14,4275 5250,4312.86 J11.2@5250,4350
NetJ14_1: J14.1 S1.3 | length 733.2
  Top Layer w100: S1.3@234.52,3730 335,3730 553.11,3511.89 J14.1@553.11,3400
  Power Layer w100: S1.3@234.52,3730 340,3730 ; J14.1@553.11,3400 553.11,3506.89
NetJ15_1: J15.1 R95.2 R97.2 | length 186.9
  Top Layer w30: R95.2@4700,4300.41 R97.2@4764,4300.41 ; R97.2@4774,4300.41 4839.16,4300.41 J15.1@4880,4341.25
NetJ18_1: J18.1 R100.1 | length 138.6
  Top Layer w10: R100.1@6355,320 6400,275 J18.1@6400,200
NetJ33_1: J33.1 R83.2 | length 169.5
  Top Layer w10: J33.1@6050,2300 6211.01,2300 R83.2@6217.01,2306
NetJ34_2: J34.2 U6.4 | length 107.1
  Top Layer w15: U6.4@7225,610 U6.4@7229,610 7325,610 J34.2@7330,605
NetQ1_1: Q1.1 R1.1 | length 66.8
  Top Layer w10: Q1.1@1087.35,4035.2 1122.8,4035.2 R1.1@1145,4012.99
NetQ2_1: Q2.1 R2.1 | length 73.7
  Top Layer w10: R2.1@2933,1127 2994,1127 Q2.1@3003,1118
NetR1_2: R1.2 U3.6 | length 3747.8
  Top Layer w10: R1.2@1145,3950 v3(1265.43,3950) ; v3(1450,3725) 1450,3504.38 1480,3474.38 1480,2440 1520,2400 1712.4,2400 2115,1997.4 2115,1500 2193.25,1421.75 2193.25,1306.75 2350,1150 U3.6@2615.43,1150
  Bottom Layer w10: v3(1265.43,3950) 1450,3765.43 v3(1450,3725)
NetR2_2: R2.2 U3.8 | length 154.7
  Top Layer w10: U3.8@2831.09,1098.91 U3.8@2830,1100 2864.98,1100 2890,1125.02 2890,1146.99 R2.2@2933,1189.99
NetR22_1: R22.1 R26.2 U2.12 | length 786.4
  Top Layer w10: R22.1@3470,1330 R26.2@3470,1250 3510,1210 3720,1210 3720.69,1210.68 3865.69,1210.68 v1(3895,1240) ; U2.12@4034.3,1236 v1(4090,1236)
  Bottom Layer w10: v1(3895,1240) 3899,1236 v1(4090,1236)
NetR23_2: R23.2 R37.2 U1.5 | length 176.1
  Top Layer w15: U1.5@2598.86,3060 R23.2@2680,3060 R37.2@2680,2965
NetR24_1: R24.1 R27.2 U2.2 | length 359
  Top Layer w10: R27.2@3570,1250 R24.1@3570,1320 ; R24.1@3570,1330 R24.1@3570,1320 ; U2.2@3821.7,1386 3786,1386 3770,1370 3620,1370 R24.1@3570,1320
NetR25_1: R25.1 R28.2 U2.5 | length 246
  Top Layer w10: R25.1@3676,1336 R25.1@3670,1330 R28.2@3670,1250 3755,1250 3769,1236 U2.5@3821.7,1236
NetR32_1: R32.1 R35.2 U3.5 | length 328.6
  Top Layer w10: R32.1@2400,1360 R35.2@2400,1280 2440,1240 2564,1240 2604,1200 U3.5@2615.43,1200
NetR33_1: R33.1 R36.2 U3.9 | length 509.5
  Top Layer w10: R36.2@2500,1280 2500,1326 ; R33.1@2500,1360 2500,1326 ; U3.9@2830,1150 2787.3,1150 2765,1172.3 2765,1217.72 2657.72,1325 2501,1325 2500,1326
NetR44_1: R44.1 R45.2 R54.1 U2.9 U2.10 U2.11 | length 773.9
  Top Layer w10: R54.1@3680,1075 3690,1085 v1(3745,1085) ; v1(4055,1045) 4034.3,1065.7 U2.9@4034.3,1086 U2.10@4034.3,1136 U2.11@4034.3,1186 4141,1186 R45.2@4160,1205 R44.1@4160,1300
  Bottom Layer w10: v1(3745,1085) 4015,1085 v1(4055,1045)
NetR71_2: R71.2 R72.2 U6.1 | length 150.5
  Top Layer w15: R72.2@7045,610 7045,684.8 U6.1@7120.73,684.8
NetR87_2: R87.2 U7.3 | length 172.8
  Top Layer w12: U7.3@5046.14,3943.24 5077.93,3943.24 5115,3906.17 5115,3870 5138.97,3846.03 R87.2@5157.44,3846.03
NetR88_1: R88.1 R90.2 U7.5 | length 168.4
  Top Layer w10: U7.5@5046.14,3994.42 5157.44,3994.42 ; R88.1@5157.44,3956.03 5157.44,3994.42 ; R90.2@5157.44,4013.15 5157.44,3994.42
NetR89_2: R89.2 U7.4 | length 139.4
  Top Layer w10: U7.4@5046.14,3968.83 5089.64,3968.83 R89.2@5157.44,3901.03
NetR91_2: R91.2 U7.6 | length 121.1
  Top Layer w10: U7.6@5056.14,4020.01 5087.09,4020.01 5135,4067.92 5156.89,4067.92 R91.2@5157.44,4067.92
NetR92_2: R92.2 U7.7 | length 128.1
  Top Layer w10: U7.7@5056.14,4045.6 5077.57,4045.6 R92.2@5153,4121.03
NetR93_2: R93.2 U7.16 | length 524.8
  Top Layer w12: U7.16@4813.86,3892.06 4813.86,3742.22 4826.08,3730 5093.85,3730 R93.2@5157.44,3793.59
NetU3_1: U3.1 U3.2 U3.11 | length 306
  Top Layer w10: U3.1@2615.43,1400 U3.2@2615.43,1350 2670,1350 2770,1250 U3.11@2830,1250
NetU3_3: U3.3 U3.4 | length 50
  Top Layer w10: U3.4@2615.43,1250 U3.3@2615.43,1300
nFLT1_H: J3.6 R8.2 R9.1 | length 2589.5
  Top Layer w10: R8.2@2155,2505 R9.1@2245,2505 2245,2535 2340,2630 2725,2630 2805,2710 2805,3853.64 v1(2540.64,4118)
  Bottom Layer w10: v1(2540.64,4118) 2500,4158.64 2500,4350 J3.6@2550,4400
nFLT1_L: J3.8 R10.2 R11.1 | length 2301
  Top Layer w10: R10.2@2515,2505 R11.1@2605,2505 2605,2535 2640,2570 2760,2570 2855,2665 ; v1(2631,4142) 2631,4126 2630,4125 2855,3900 2855,2665 ; 2855,2680 2855,2665
  Bottom Layer w10: v1(2631,4142) 2631,4149 2600,4180 2600,4350 J3.8@2650,4400
nFLT2_H: J3.4 R6.2 R7.1 | length 2532
  Top Layer w10: R6.2@2335,2505 2415,2505 R7.1@2425,2515 ; R7.1@2425,2505 R7.1@2425,2515 ; J3.4@2450,4400 2400,4350 2400,4267.03 2497.03,4170 2542.99,4170 2830,3882.99 2830,2685 2745,2600 2490,2600 2425,2535 R7.1@2425,2515
nFLT2_L: J3.10 R12.2 R13.1 | length 2124.6
  Top Layer w10: R12.2@2695,2505 R13.1@2785,2505 2785,2555 2880,2650 ; v1(2720,4105) 2720,4085 2880,3925 2880,2650 ; 2880,2655 2880,2650
  Bottom Layer w10: v1(2720,4105) 2700,4125 2700,4350 J3.10@2750,4400
nSTB2: J2.46 J13.2 | length 2704.8
  Top Layer w10: J13.2@1579.98,2150 1634.98,2095 1848.25,2095 2065,1878.25 2065,1212.32 2372.32,905 3014,905 3034,925 3290,925 3340,875 J2.46@3350,875
O_ASC_EN: R15.2 U2.4 | length 1794.2
  Top Layer w10: v4(3280,2180) 3280,2348.6 3325,2393.6 R15.2@3325,2425 ; v1(3600,2180) 3600,2175 3595,2170 3595,2085 3620,2060 3664.25,2060 3925,1799.25 3925,1638.46 3745,1458.46 v1(3745,1410) ; v1(3745,1330) 3745,1302.85 3761.85,1286 U2.4@3821.7,1286
  Bottom Layer w10: v4(3280,2180) 3292.72,2167.28 3587.28,2167.28 v1(3600,2180) ; v1(3745,1330) v1(3745,1410)
O_ASC_H: R17.2 U2.14 | length 1889.4
  Top Layer w10: R17.2@2965,2425 2965,2393.09 2990,2368.09 2990,2190 v4(3040,2140) ; v1(3630,2099.02) 3655.98,2099.02 3950,1805 3950,1385 3999,1336 U2.14@4034.3,1336
  Bottom Layer w10: v4(3040,2140) 3062.69,2117.31 3611.71,2117.31 v1(3630,2099.02)
O_ASC_L: R19.2 U2.15 | length 1671
  Top Layer w10: R19.2@3145,2425 3145,2210 v4@3193.7,2161.3 ; v1(3630,2145) 3640,2145 3975,1810 3975,1410 3999,1386 U2.15@4034.3,1386
  Bottom Layer w10: v4(3200,2155) 3210,2145 v1(3630,2145)
OUT1: R96.1 U7.8 | length 201.9
  Top Layer w17: U7.8@5050,4077.34 U7.8@5056.14,4071.2
  Top Layer w25: U7.8@5050,4077.34 5050,4089.18 5160.04,4199.22 R96.1@5160.04,4225
OUT2: R97.1 U7.10 | length 239.2
  Top Layer w17: 4776.4,4045.6 U7.10@4813.86,4045.6
  Top Layer w18: 4764,4071.92 4764,4058 4776.4,4045.6
  Top Layer w25: 4764,4064.96 R97.1@4764,4235.29
PGOOD1: J20.10
PGOOD2: J21.10
PWMF: J5.26 R63.1 R65.1 | length 2820.3
  Top Layer w10: R63.1@7087.99,900 R65.1@7087.99,974 7174,974 7665,1465 8935,1465 v1(9000,1400) ; J5.26@9260.24,1700 v1(9365,1700) v1@9375,1700
  Bottom Layer w10: v1(9000,1400) 9065,1400 v1(9365,1700)
RX_ISO: J2.2
RxD2: J2.44 J13.6 | length 2936.9
  Top Layer w10: J13.6@1579.98,2350 1629.98,2300 1760,2300 2090,1970 2090,1220 2385,925 3000,925 3020,945 3380,945 J2.44@3450,875
SM_ADINA4: J2.65 U4.13 | length 585.8
  Top Layer w10: v1@4880,252.8 U4.13@4924.56,252.8
  Bottom Layer w10: v1(4870,252.8) 4907.2,290 4990.43,290 5080,379.57 5080,630 J2.65@5100,650
SM_ADINA5: J2.67
SM_ADINA6: J2.69
SM_ADINA7: J2.71
SM_ADINB4: J2.15 U4.3 | length 835.4
  Top Layer w10: U4.3@4692.28,278.39 v1(4755,278.39) v1@4760,278.39
  Bottom Layer w10: v1@4760,278.39 4838.39,278.39 4873.74,313.74 4975,313.74 5050,388.74 5050,661.06 5100,711.06 J2.15@5100,800
SM_GPIO0: J2.23 R7.2 | length 3708.7
  Top Layer w10: R7.2@2425,2425 2425,2384.31 2519.31,2290 v1(2750,2290) ; v1(3365,2278.91) 3388.91,2278.91 3550,2440 4090,2440 4220,2310 4220,2045 4145,1970 4145,1648.38 4315,1478.38 4315,1169.5 4525,959.5 4525,825 J2.23@4500,800
  Bottom Layer w10: v1(2750,2290) 3353.91,2290 v1(3365,2278.91)
SM_GPIO1: J2.73 R13.2 | length 3538.2
  Top Layer w10: R13.2@2785,2425 2785,2392.4 2824.97,2352.43 v1(2841.75,2352.43) ; v4@3386,2365 3416.24,2365 3531.24,2480 4110,2480 4260,2330 4260,2015 4185,1940 4185,1671.21 4355,1501.21 4355,1190 4570,975 4570,720 J2.73@4500,650 ; v1(2841.75,2352.43) 2842.09,2352.09 2842.43,2352.43 v1(2841.75,2352.43)
  Bottom Layer w10: v1(2841.75,2352.43) 3317.43,2352.43 3323.71,2358.71 3384.71,2358.71 v4(3386,2360)
SM_GPIO2: J2.24 R9.2 | length 3767.1
  Top Layer w10: R9.2@2245,2425 2245,2385 2415,2215 2825,2215 v4@2825,2205 ; v4(3358.01,2205) 3380,2205 3545,2370 3950,2370 3964.97,2384.97 4085.03,2384.97 4180,2290 4180,2072.77 4105,1997.77 4105,1625 4270,1460 4270,1140 4450,960 J2.24@4450,875
  Bottom Layer w10: v4@2825,2205 v4@2827.5,2207.5 ; v4@2830,2205 v4(2830,2210) 2833.84,2213.84 3349.17,2213.84 v4(3358.01,2205)
SM_GPIO3: J2.74 R11.2 | length 3673.4
  Top Layer w10: R11.2@2605,2425 2605,2390 2635,2360 v1(2657.5,2360) ; v4@3350,2325 v4(3355,2325) 3405,2325 3540,2460 4100,2460 4240,2320 4240,2030 4165,1955 4165,1662.93 4335,1492.93 4335,1180 4547.57,967.43 4547.57,777.57 4495,725 J2.74@4450,725
  Bottom Layer w10: v1(2657.5,2360) 2752.02,2360 2794.59,2317.43 3347.43,2317.43 v4(3355,2325)
SM_GPIO6: J2.26 R20.1 R21.1 | length 1582.1
  Top Layer w10: R20.1@3735,2140.83 R21.1@3840,2140.83 3840,1980 4000.03,1819.97 4000.03,1634.97 4210,1425 4210,1095 4325,980 4325,900 J2.26@4350,875
SM_GPIO7: J2.76 U2.13 | length 865.2
  Top Layer w10: U2.13@4034.3,1286 4000,1286 3980,1266 3980,1060 4055,985 4240,985 4300,925 4300,860 4350,810 J2.76@4350,725
SM_GPIO8: J2.28 U2.1 | length 854
  Top Layer w10: U2.1@3821.7,1436 3859,1436 3955,1340 3955,1045 4040,960 4200,960 4250,910 J2.28@4250,875
SM_GPIO9: J2.78 U2.3 | length 896.7
  Top Layer w10: U2.3@3821.7,1336 3870.54,1336 3930,1276.54 3930,1034 4029,935 4165,935 4200,900 4200,861 4250,811 J2.78@4250,725
SM_GPIO10: J2.29 U4.10 | length 1232.6
  Top Layer w10: J2.29@4200,800 4200,715 4250,665 4250,615.57 4355.57,510 4825,510 4850,485 4850,305 4835,290 4835,229.57 4888.54,176.02 U4.10@4924.56,176.02
SM_GPIO11: J2.79 U4.9 | length 1121.4
  Top Layer w10: J2.79@4200,650 4200,610 4325,485 4815,485 4825,475 4825,330 4815,320 4815,215 4879.57,150.43 U4.9@4924.56,150.43
SM_GPIO13: J2.83
SM_GPIO16: J2.38 J22.8 | length 2090
  Top Layer w10: v1(2400,1010) 2410,1010 2435,985 3410,985 3445,950 3705,950 3750,905 J2.38@3750,875
  Bottom Layer w10: J22.8@1779.98,1122.3 1827.28,1075 1915,1075 1945,1045 2365,1045 v1(2400,1010)
SM_GPIO17: J2.88 J22.10 | length 2423.6
  Top Layer w10: J22.10@1779.98,1222.3 1829.98,1172.3 1907.7,1172.3 1965,1115 1965,1055 2480,540 3666,540 3750,624 J2.88@3750,725
SM_GPIO18: J2.39 J22.5 | length 1978.4
  Top Layer w10: v4@2405,955 2415,965 3400,965 3440,925 3674,925 3700,899 J2.39@3700,800
  Bottom Layer w10: J22.5@1879.98,1022.3 2337.7,1022.3 v4@2405,955
  other v4: 2405,960
SM_GPIO19: J2.89 J22.12 | length 2349.4
  Top Layer w10: J22.12@1779.98,1322.3 1832.28,1270 1910.33,1270 1985,1195.33 1985,1065 2490,560 3610,560 J2.89@3700,650
SM_GPIO20: J2.40
SM_GPIO21: J2.90
SM_GPIO22: J2.41
SM_GPIO23: J2.91 R29.1 R81.2 U3.13 | length 1713.5
  Top Layer w10: U3.13@2830,1350 2905.09,1350 R81.2@2930.09,1325 ; v1(2910,845) 2910,770 3100,580 3530,580 J2.91@3600,650 ; v4(2937.19,1280.09) 2933.64,1276.54 2930.09,1280.09 R81.2@2930.09,1325 ; R29.1@3099,1330 R29.1@3110,1330 3070,1370 2970.09,1370 R81.2@2930.09,1330 R81.2@2930.09,1325
  Bottom Layer w10: v1(2910,845) 2910,1252.9 v4(2937.19,1280.09)
SM_GPIO24: J2.35 R34.1 U3.10 | length 1569.1
  Top Layer w10: U3.10@2830,1200 2865,1200 2890,1225 2970,1225 3035,1160 3404.06,1160 ; R34.1@3370,1330 3404.06,1295.94 3404.06,1160 ; v1(3765,1035) 3755,1025 3647.7,1025 3640,1032.7 3640,1120 3633,1127 3419.04,1127 3404.06,1141.99 3404.06,1160
  Bottom Layer w10: v1(3765,1035) 3900,900 J2.35@3900,800
SM_GPIO26: J2.36
SM_GPIO27: J2.86
SM_GPIO31: J2.94 J13.4 | length 3279.2
  Top Layer w10: J13.4@1579.98,2250 1525,2195.02 1525,2120 1575,2070 1835.02,2070 2040,1865.02 2040,1205 2360,885 3015,885 3100,800 3100,665 3165,600 3417.79,600 3450,632.21 J2.94@3450,725
SM_GPIO58: J2.18
SM_GPIO59: J2.68 R72.1 | length 2518.7
  Top Layer w10: J2.68@4950,725 4950,605 5100,455 5220,455 5308.78,366.22 5308.78,291.22 5315,285 5575,285 5580,290 5580,375 5705,500 6370.58,500 v3(6380,509.42) ; v3(6600,590) 6960,590 R72.1@6980,610
  Bottom Layer w10: v3(6380,509.42) 6389.42,500 6470,500 6490.25,520.25 6560,590 v3(6600,590)
SM_GPIO60: J2.20 R86.1 | length 1833.8
  Top Layer w10: R86.1@4100,2137.77 4100,2057.2 4065,2022.2 4065,1600 4230,1435 4230,1110 4365,975 v10(4365,965)
  Bottom Layer w10: v10(4365,965) 4370,960 4765,960 J2.20@4850,875
SM_GPIO61: J2.70
SM_GPIO62: J2.22
SM_GPIO63: J2.72
SM_GPIO84: J2.31
SM_GPIO85: J2.81 U4.6 | length 999.8
  Top Layer w10: J2.81@4100,650 4110,650 4305,455 4605,455 4690.59,369.41 4725.59,369.41 4790,305 4790,260 4731.61,201.61 U4.6@4692.28,201.61
SM_TCK: J2.48
SM_TDI: J2.97
SM_TDO: J2.98
SM_TMS: J2.49
SM_TRST: J2.99
SPI_CS_1: J22.14
TX_ISO: J2.52
VBAT: C20.1 C21.1 C22.1 D7.1 J20.2 J20.4 J21.2 J21.4 J24.1 J30.2 R31.2 R55.1 S1.2 U7.11 | length 4424.4
  Top Layer w17: 4731.18,4020.01 4760.27,4020.01 U7.11@4813.86,4020.01
  Top Layer w20: 4706.55,4073.73 4710.14,4070.14 4760.27,4020.01
  Top Layer w30: v8@4570,3747 v8(4572,3749) 4618,3795 C20.1@4725.04,3795
  Top Layer w40: J24.1@679.98,422.3 679.98,489.98 940,750 v2(2150,750) ; v2(2285,825) R55.1@2355,825 ; 4643.44,4003.44 4710.14,4070.14 ; 4706.55,4073.73 C21.1@4706.55,4146.03
  Power Layer w40: J30.2@2400,3900 2400,3893.75 2527.31,3766.43 3113.57,3766.43 3330,3550 3640,3550 3656.61,3566.61 3656.61,3671.61 3675.81,3690.81 4077.21,3690.81 4135.4,3749
  Bottom Layer w10: v2(2150,750) v2@2164.25,750 ; v2@2157.13,757.13 v2@2164.25,750 ; v2@2164.63,749.63 v2@2164.25,750
  Bottom Layer w40: v2@2157.13,757.13 2225,825 v2(2285,825)
  other v8: 4222.93,3749 4332,3749 4452,3749
Vdc2_N: J5.2 J16.4 | length 3772.9
  Top Layer w15: J16.4@6700,3600 6745,3645 6745,3676.97 6774.64,3706.62 7058.56,3706.62 7100,3665.18 v1(7100,2955.44) v1@7094.56,2950 ; v1(7410,2955.44) 7410,2955 7415,2950 8785,2950 9192.62,2542.38 9192.62,2305.2 9197.82,2300 J5.2@9260.24,2300
  Bottom Layer w15: v1(7100,2955.44) 7105.44,2950 7404.56,2950 v1(7410,2955.44)
Vdc2_P: J5.1 J16.3 | length 3697.8
  Top Layer w15: J16.3@6800,3600 6770,3630 6770,3666.62 6785,3681.62 7048.21,3681.62 7075,3654.82 7075,2980 7065,2970 7065,2940 7080,2925 7094.56,2925 v1(7100,2919.56) ; v1(7410,2919.56) 7410,2920 7415,2925 8774.64,2925 9167.62,2532.03 9167.62,2305.2 9162.42,2300 J5.1@9100,2300
  Bottom Layer w15: v1(7100,2919.56) 7105.44,2925 7404.56,2925 v1(7410,2919.56)
Vdc_N: J6.14 J16.6 | length 3284.5
  Top Layer w15: J16.6@6500,3600 6505.37,3600 6534.11,3628.74 6534.11,3654.82 6541.44,3662.15 6744.29,3865 8465,3865 8775,4175 8775,4450 8750,4475 8400,4475 8375,4450 8375,4425 J6.14@8400,4400
Vdc_P: J6.13 J16.5 | length 3484.5
  Top Layer w15: J16.5@6600,3600 6587.85,3600 6559.11,3628.74 6559.11,3644.47 6754.64,3840 8475.36,3840 8510.36,3875 8800,4164.64 8800,4460.36 8767.68,4492.68 8760.36,4500 8389.64,4500 8382.32,4492.68 8350,4460.36 8350,4350 J6.13@8400,4300
Vfb_Io: J5.12 R56.1 R58.1 | length 2745.9
  Top Layer w10: R56.1@7087.99,1270 R58.1@7087.99,1340 7225,1340 7595,1710 8710,1710 v1(8900,1900) ; J5.12@9260.24,2050 v1(9365,2050)
  Bottom Layer w10: v1(8900,1900) 8935.37,1935.37 9122.57,1935.37 9237.2,2050 v1(9365,2050)
Vfb_Io2: J5.14 R59.1 | length 2714.3
  Top Layer w10: R59.1@7087.99,1200 7125,1200 7610,1685 8723.07,1685 8888.07,1850 v1(8900,1850) ; J5.14@9260.24,2000 v1(9365,2000)
  Bottom Layer w10: v1@8900,1847.09 8962.91,1910 9135,1910 9225,2000 v1(9365,2000)
VIN2: J21.3 J21.5 | length 100
  Top Layer w40: J21.3@900,4300 J21.5@1000,4300
VIN_SMCU: J2.77 J2.82 J2.87 J2.92 J2.96 R55.2 | length 87.8
  Top Layer w40: R55.2@2435,825 v2(2522.79,825)
VIS1: J20.1
VIS2: J21.1
VREF_HI: J2.66
VREF_LO: J2.16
